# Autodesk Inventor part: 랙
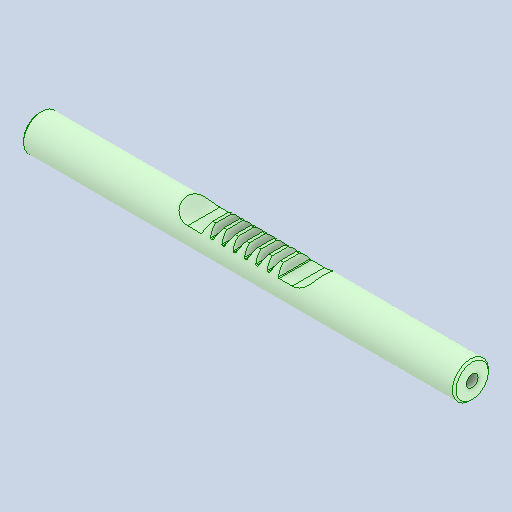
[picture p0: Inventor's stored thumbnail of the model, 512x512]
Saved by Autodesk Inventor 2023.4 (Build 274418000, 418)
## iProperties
Created: 2024-05
Part Number: 랙
Material: 강철, 탄소
Document SubType Name: Modeling
Designer: edu-40
Density: 7.85 g/cm^3
Appearance: 기본값
Author: jhkim
Sending System: Autodesk Inventor 2025
Preprocessor: ST-DEVELOPER v20
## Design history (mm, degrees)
feature "솔리드1"
node "솔리드2"
